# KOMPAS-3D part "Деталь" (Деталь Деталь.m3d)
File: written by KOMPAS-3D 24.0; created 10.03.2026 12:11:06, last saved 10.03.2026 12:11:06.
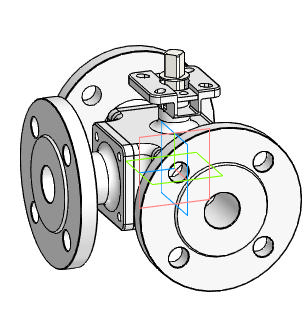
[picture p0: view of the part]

Document properties: Автор: R2D2; Полное имя файла: E:\Работа\Зайцев\BV3232P(4pc)-FP-3WL-F-ISO-H Кран шаровой DN.ru Ду15-100 Ру16\DN25\исходные материалы\Деталь Деталь.m3d

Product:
- Body: Твердое тело1  | qty 1
- Part/product: Деталь
    additional columns: Типовые

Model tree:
1. Твердое тело1  (labels: Твердое тело1)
